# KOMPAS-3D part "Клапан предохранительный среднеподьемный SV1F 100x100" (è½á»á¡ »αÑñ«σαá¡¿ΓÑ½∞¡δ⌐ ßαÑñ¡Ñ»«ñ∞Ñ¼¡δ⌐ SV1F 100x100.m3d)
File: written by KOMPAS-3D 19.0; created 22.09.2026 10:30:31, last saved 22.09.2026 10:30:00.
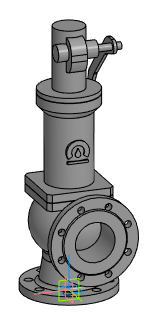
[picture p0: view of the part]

Document properties: Автор: Евгений; Полное имя файла: Z:\3.Личные\sachek\Dendor\_3D для проектировщиков\5.8 SV1F. Клапан предохранительный среднеподьемный\SV1F_STP\Клапан предохранительный среднеподьемный SV1F 100x100.m3d

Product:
- Part/product: Клапан предохранительный среднеподьемный SV1F 100x100
    Масса: 88.6628

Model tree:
1. Операция без истории:1  (labels: Клапан предохранительный среднеподьемный SV1F 100x100)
